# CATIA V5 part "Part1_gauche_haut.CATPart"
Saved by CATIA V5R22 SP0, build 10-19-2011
Part number: Part1
Bounding box of the stored display mesh (mm): x -87.5 to 0, y -87.5 to 4.5, z 150 to 302
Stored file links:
  C:\Users\dussa\Documents\ENIB\S5\inter\Part1_gauche_haut.CATPart
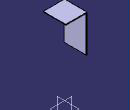
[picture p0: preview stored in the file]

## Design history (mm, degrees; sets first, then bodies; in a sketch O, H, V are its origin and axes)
Body1 (main body)
  Sketch1 on xy-plane, origin (0, 0, 0), H (1, 0, 0), V (0, 1, 0)
    line L1 (-87.5, 87.5) -> (87.5, 87.5)
    line L2 (87.5, 87.5) -> (87.5, -87.5)
    line L3 (87.5, -87.5) -> (-87.5, -87.5)
    line L4 (-87.5, -87.5) -> (-87.5, 87.5)
    distance L1 L3 = 175
    distance L4 L2 = 175
    horizontal: L1 H, L3 H
    vertical: L2 V, L4 V
    symmetry: L3 L1 H, L4 L2 V
  Pad1: profile Sketch1, direction (0, 0, 1), length 2
  Sketch2 on face of Pad1 from Sketch1.L2, origin (87.5, 0, 0), H (0, 1, 0), V (0, 0, 1)
    point P1 (-87.5, 0)
    line L1 (-87.5, 0) -> (87.5, 0)
    line L2 (87.5, 0) -> (87.5, 62.3217)
    line L3 (-87.5, 80) -> (-87.5, 0)
    point P3 (87.5, 62.3217)
    point P4 (-87.5, 80)
    reference projected line E1 (-87.5, 0) -> (-87.5, 2) from edge [face of Pad1 from Sketch1.L2 | face of Pad1 from Sketch1.L3]
    reference projected line E2 (87.5, 0) -> (87.5, 2) from edge [face of Pad1 from Sketch1.L1 | face of Pad1 from Sketch1.L2]
    reference projected line E3 (-87.5, 0) -> (87.5, 0) from edge [start face of Pad1 | face of Pad1 from Sketch1.L2]
    line L4 (-87.5, 300) -> (2.5, 300)
    line L5 (2.5, 300) -> (2.5, 115)
    line L6 (-87.5, 80) -> (-87.5, 300)
    point P8 (-87.5, 80)
    line L7 (2.5, 115) -> (87.5, 62.3217)
    point P9 (87.5, 62.3217)
    distance P4 P1 = 80
    distance L1 L4 = 300
    length L5 = 185
    distance L5 L6 = 90
    length L7 = 100
    horizontal: L1 H, L4 H
    vertical: L2 V, L3 V, L5 V, L6 V
    coincidence: E1 L3, L2 E2, L1 E3, L6 L3, P8 P4, L7 P3, P3 P9
  Pad2: profile Sketch2, direction (1, 0, 0), length 2
  Sketch3 on face of Pad1 from Sketch1.L4, origin (-87.5, 0, 0), H (0, 1, 0), V (0, 0, 1)
    point P1 (-87.5, 0)
    line L1 (-87.5, 0) -> (87.5, 0)
    line L2 (87.5, 0) -> (87.5, 62.3217)
    line L3 (-87.5, 80) -> (-87.5, 0)
    point P3 (87.5, 62.3217)
    point P4 (-87.5, 80)
    reference projected line E1 (-87.5, 0) -> (-87.5, 2) from edge [face of Pad1 from Sketch1.L2 | face of Pad1 from Sketch1.L3]
    reference projected line E2 (87.5, 0) -> (87.5, 2) from edge [face of Pad1 from Sketch1.L1 | face of Pad1 from Sketch1.L2]
    reference projected line E3 (-87.5, 0) -> (87.5, 0) from edge [start face of Pad1 | face of Pad1 from Sketch1.L2]
    line L4 (-87.5, 300) -> (2.5, 300)
    line L5 (2.5, 300) -> (2.5, 115)
    line L6 (-87.5, 80) -> (-87.5, 300)
    point P8 (-87.5, 80)
    line L7 (2.5, 115) -> (87.5, 62.3217)
    point P9 (87.5, 62.3217)
    distance P4 P1 = 80
    distance L1 L4 = 300
    length L5 = 185
    distance L5 L6 = 90
    length L7 = 100
    horizontal: L1 H, L4 H
    vertical: L2 V, L3 V, L5 V, L6 V
    coincidence: E1 L3, L2 E2, L1 E3, L6 L3, P8 P4, L7 P3, P3 P9
  Pad3: profile Sketch3, direction (1, 0, 0), length 2
  Sketch4 on face of Pad3 from Sketch3.L4, origin (0, 0, 300), H (1, 0, 0), V (0, 1, 0)
    line L1 (-87.5, 2.5) -> (89.5, 2.5)
    line L2 (89.5, 2.5) -> (89.5, -87.5)
    line L3 (89.5, -87.5) -> (-87.5, -87.5)
    line L4 (-87.5, -87.5) -> (-87.5, 2.5)
    reference projected line E1 (-87.5, -87.5) -> (87.5, -87.5) from edge [face of Pad3 | end face of Pad1]
    reference projected point E2 (89.5, 2.5) from vertex [face of Pad2 from Sketch2.L5 | face of Pad2 from Sketch2.L4 | end face of Pad2]
    reference projected line E3 (-87.5, 2.5) -> (-87.5, -87.5) from edge [start face of Pad3 | face of Pad3 from Sketch3.L4]
    reference projected line E4 (89.5, 2.5) -> (89.5, -87.5) from edge [face of Pad2 from Sketch2.L4 | end face of Pad2]
    horizontal: L1 H, L3 H
    vertical: L2 V, L4 V
    coincidence: L3 E1, L1 E2, L4 E3, E4 L2
  Pad4: profile Sketch4, direction (0, 0, 1), length 2
  Sketch5 on face of Pad3, origin (0, 87.5, 0), H (-1, 0, 0), V (0, 0, 1)
    line L1 (-89.5, 62.3217) -> (87.5, 62.3217)
    line L2 (87.5, 62.3217) -> (87.5, 0)
    line L3 (87.5, 0) -> (-89.5, 0)
    line L4 (-89.5, 0) -> (-89.5, 62.3217)
    reference projected point E1 (85.5, 62.3217) from vertex [end face of Pad3 | face of Pad3 from Sketch3.L2 | face of Pad3 from Sketch3.L7]
    reference projected line E2 (-87.5, 0) -> (87.5, 0) from edge [face of Pad3 | face of Pad3]
    reference projected line E3 (87.5, 0) -> (87.5, 2) from edge [face of Pad3 | face of Pad3]
    reference projected line E4 (-89.5, 0) -> (-89.5, 62.3217) from edge [face of Pad3 | end face of Pad2]
    horizontal: L1 H, L3 H
    vertical: L2 V, L4 V
    coincidence: E1 L1, E2 L3, L2 E3, E4 L4
  Pad5: profile Sketch5, direction (0, 1, 0), length 2
  Sketch6 on face of Pad2 from Sketch2.L7, origin (0, 52.1868, 84.2069), H (-1, 0, 0), V (0, -0.85, 0.5268)
    line L1 (-89.5, 58.455) -> (87.5, 58.455)
    line L2 (87.5, 58.455) -> (87.5, -43.245)
    line L3 (87.5, -43.245) -> (-89.5, -43.245)
    line L4 (-89.5, -43.245) -> (-89.5, 58.455)
    reference projected line E1 (87.5, -43.245) -> (-89.5, -43.245) from edge [face of Pad5 from Sketch5.L1 | end face of Pad5]
    reference projected line E2 (87.5, -41.545) -> (87.5, 58.455) from edge [face of Pad5 | face of Pad3 from Sketch3.L7]
    reference projected line E3 (87.5, 58.455) -> (85.5, 58.455) from edge [face of Pad3 from Sketch3.L5 | face of Pad3 from Sketch3.L7]
    reference projected line E4 (-89.5, -41.545) -> (-89.5, 58.455) from edge [face of Pad2 from Sketch2.L7 | face of Pad5]
    circle A1 centre (-50, 11.755) radius 14.5
    point P5 (-50, 11.755)
    circle A2 centre (50, 11.755) radius 3.35
    point P6 (50, 11.755)
    radius A1 = 14.5
    radius A2 = 3.35
    distance P5 V = 50
    distance P6 V = 50
    distance P5 L3 = 55
    distance P6 L3 = 55
    horizontal: L1 H, L3 H
    vertical: L2 V, L4 V
    coincidence: L3 E1, L2 E2, E3 L1, L4 E4
  Pad6: profile Sketch6, direction (0, 0.5268, 0.85), length 2
  Sketch7 on face of Pad3 from Sketch3.L5, origin (0, 2.5, 0), H (-1, 0, 0), V (0, 0, 1)
    line L1 (-89.5, 302) -> (87.5, 302)
    line L2 (87.5, 302) -> (87.5, 116.7)
    line L3 (87.5, 116.7) -> (-89.5, 116.7)
    line L4 (-89.5, 116.7) -> (-89.5, 302)
    reference projected line E1 (-89.5, 302) -> (87.5, 302) from edge [face of Pad4 from Sketch4.L1 | end face of Pad4]
    reference projected line E2 (87.5, 116.7) -> (-89.5, 116.7) from edge [face of Pad6 from Sketch6.L1 | end face of Pad6]
    reference projected line E3 (-89.5, 115) -> (-89.5, 300) from edge [face of Pad2 from Sketch2.L5 | face of Pad6]
    reference projected line E4 (87.5, 115) -> (87.5, 300) from edge [face of Pad6 | face of Pad3 from Sketch3.L5]
    line L5 (-86, 298.5) -> (84, 298.5)
    line L6 (84, 298.5) -> (84, 128.5)
    line L7 (84, 128.5) -> (-86, 128.5)
    line L8 (-86, 128.5) -> (-86, 298.5)
    distance L6 L8 = 170
    distance L5 L7 = 170
    distance L5 L1 = 3.5
    distance L8 L4 = 3.5
    horizontal: L1 H, L3 H, L5 H, L7 H
    vertical: L2 V, L4 V, L6 V, L8 V
    coincidence: L1 E1, L3 E2, L4 E3, L2 E4
  Pad7: profile Sketch7, direction (0, 1, 0), length 2
  Split1: SplitPlane {plane type Offset, RefPlane yz-plane, Offset 0}
  Split2: SplitPlane {plane type Offset, Offset 150, RefPlane xy-plane}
